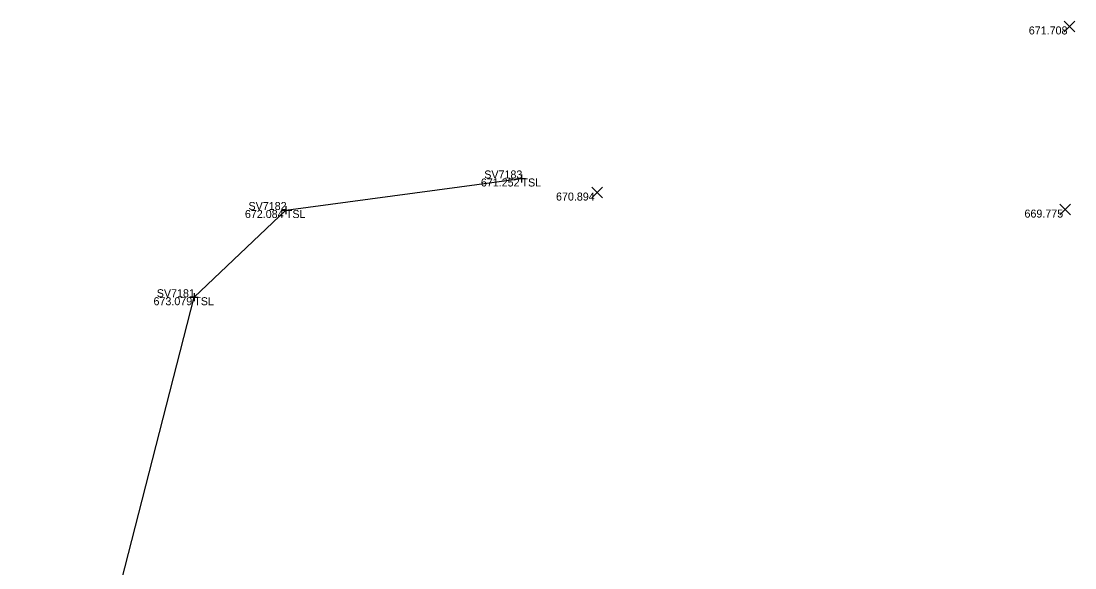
# Model space of a CAD drawing. Extents: x 1660019 to 1662995, y 619975 to 620342.
# Drawn here: x 1661477.1 to 1661608.8, y 620253.7 to 620322 of the extents above; entities that cross this region are included whole.
import ezdxf

# ---------------------------------------------------------------- set-up
doc = ezdxf.new("R2010")
doc.units = 0
for name, color, linetype in [('BR_X_Rail_Object', 7, 'Continuous'), ('RD_P_GR_Lt', 7, 'Continuous'), ('RD_P_GR_Rt', 7, 'Continuous'), ('RD_X_GR_Bar', 7, 'Continuous'), ('RD_X_Wall', 7, 'Continuous'), ('SV_X_Toe_of_Slope', 7, 'Continuous')]:
    doc.layers.add(name, color=color, linetype=linetype)

msp = doc.modelspace()

# ---------------------------------------------------------------- linework, layer by layer
at = {"layer": 'RD_P_GR_Lt'}
for p, q in [((1661539.69, 620302.82), (1661539.69, 620301.82)), ((1661539.19, 620302.32), (1661540.19, 620302.32)), ((1661539.69, 620302.32), (1661539.69, 620302.32)), ((1661510.24, 620298.88), (1661510.24, 620297.88)), ((1661509.74, 620298.38), (1661510.74, 620298.38)), ((1661510.24, 620298.38), (1661510.24, 620298.38)), ((1661498.79, 620287.98), (1661498.79, 620286.98)), ((1661498.29, 620287.48), (1661499.29, 620287.48)), ((1661498.79, 620287.48), (1661498.79, 620287.48))]:
    msp.add_line(p, q, dxfattribs=at)
at = {"layer": 'RD_P_GR_Rt'}
for p, q in [((1661607.51, 620320.65), (1661608.84, 620321.99)), ((1661607.51, 620321.99), (1661608.84, 620320.65)), ((1661548.46, 620299.89), (1661549.79, 620301.23)), ((1661548.46, 620301.23), (1661549.79, 620299.89)), ((1661606.95, 620297.76), (1661608.28, 620299.09)), ((1661606.95, 620299.09), (1661608.28, 620297.76))]:
    msp.add_line(p, q, dxfattribs=at)
at = {"layer": 'SV_X_Toe_of_Slope'}
msp.add_lwpolyline([(1661490.6, 620170.61), (1661477.15, 620203.1), (1661498.79, 620287.48), (1661510.24, 620298.38), (1661539.69, 620302.32)], dxfattribs=at)

# ---------------------------------------------------------------- texts
at = {"layer": 'BR_X_Rail_Object'}
for p in [(1661539.69, 620301.32), (1661510.24, 620297.38), (1661498.79, 620286.48)]:
    msp.add_text('TSL', height=1, dxfattribs=at).set_placement(p)
at = {"layer": 'RD_X_GR_Bar'}
for s, p in [('671.708', (1661603.08, 620320.32)), ('671.252', (1661534.61, 620301.32)), ('670.894', (1661544, 620299.56)), ('672.084', (1661505.12, 620297.38)), ('669.775', (1661602.54, 620297.43)), ('673.079', (1661493.7, 620286.48))]:
    msp.add_text(s, height=1, dxfattribs=at).set_placement(p)
at = {"layer": 'RD_X_Wall'}
for s, p in [('SV7183', (1661535.03, 620302.32)), ('SV7182', (1661505.57, 620298.38)), ('SV7181', (1661494.11, 620287.48))]:
    msp.add_text(s, height=1, dxfattribs=at).set_placement(p)

doc.saveas('drawing.dxf')
